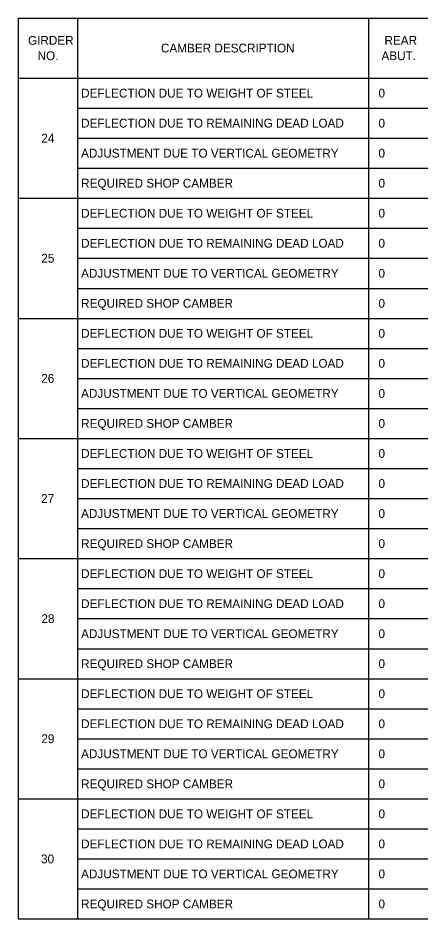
# Model space of a CAD drawing. Extents: x 3 to 33.4, y 0.9 to 20.5.
# Drawn here: x 3 to 10.19, y 4.69 to 20.5 of the extents above; entities that cross this region are included whole.
import ezdxf

# ---------------------------------------------------------------- set-up
doc = ezdxf.new("R2010")
doc.units = 0
doc.layers.add('BR_X_Beam_Object', color=7, linetype='Continuous')
doc.layers.add('BR_X_Slab_Object', color=7, linetype='Continuous')

msp = doc.modelspace()

# ---------------------------------------------------------------- linework, layer by layer
at = {"layer": 'BR_X_Slab_Object'}
for p, q in [((3, 20.5), (5.319, 20.5)), ((3, 20.5), (3, 4.688)), ((4.041, 20.5), (4.041, 4.688)), ((5.319, 20.5), (10.194, 20.5)), ((9.153, 20.5), (9.153, 4.688)), ((3, 19.446), (5.319, 19.446)), ((5.319, 19.446), (10.194, 19.446)), ((4.041, 18.919), (5.319, 18.919)), ((5.319, 18.919), (10.194, 18.919)), ((4.041, 18.392), (5.319, 18.392)), ((5.319, 18.392), (10.194, 18.392)), ((4.041, 17.865), (5.319, 17.865)), ((5.319, 17.865), (10.194, 17.865)), ((3, 17.338), (5.319, 17.338)), ((5.319, 17.338), (10.194, 17.338)), ((4.041, 16.811), (5.319, 16.811)), ((5.319, 16.811), (10.194, 16.811)), ((4.041, 16.284), (5.319, 16.284)), ((5.319, 16.284), (10.194, 16.284)), ((4.041, 15.756), (5.319, 15.756)), ((5.319, 15.756), (10.194, 15.756)), ((3, 15.229), (5.319, 15.229)), ((5.319, 15.229), (10.194, 15.229)), ((4.041, 14.702), (5.319, 14.702)), ((5.319, 14.702), (10.194, 14.702)), ((4.041, 14.175), (5.319, 14.175)), ((5.319, 14.175), (10.194, 14.175)), ((4.041, 13.648), (5.319, 13.648)), ((5.319, 13.648), (10.194, 13.648)), ((3, 13.121), (5.319, 13.121)), ((5.319, 13.121), (10.194, 13.121)), ((4.041, 12.594), (5.319, 12.594)), ((5.319, 12.594), (10.194, 12.594)), ((4.041, 12.067), (5.319, 12.067)), ((5.319, 12.067), (10.194, 12.067)), ((4.041, 11.54), (5.319, 11.54)), ((5.319, 11.54), (10.194, 11.54)), ((3, 11.013), (5.319, 11.013)), ((5.319, 11.013), (10.194, 11.013)), ((4.041, 10.486), (5.319, 10.486)), ((5.319, 10.486), (10.194, 10.486)), ((4.041, 9.959), (5.319, 9.959)), ((5.319, 9.959), (10.194, 9.959)), ((4.041, 9.432), (5.319, 9.432)), ((5.319, 9.432), (10.194, 9.432)), ((3, 8.905), (5.319, 8.905)), ((5.319, 8.905), (10.194, 8.905)), ((4.041, 8.378), (5.319, 8.378)), ((5.319, 8.378), (10.194, 8.378)), ((4.041, 7.851), (5.319, 7.851)), ((5.319, 7.851), (10.194, 7.851)), ((4.041, 7.324), (5.319, 7.324)), ((5.319, 7.324), (10.194, 7.324)), ((3, 6.796), (5.319, 6.796)), ((5.319, 6.796), (10.194, 6.796)), ((4.041, 6.269), (5.319, 6.269)), ((5.319, 6.269), (10.194, 6.269)), ((4.041, 5.742), (5.319, 5.742)), ((5.319, 5.742), (10.194, 5.742)), ((4.041, 5.215), (5.319, 5.215)), ((5.319, 5.215), (10.194, 5.215)), ((3, 4.688), (5.319, 4.688)), ((5.319, 4.688), (10.194, 4.688))]:
    msp.add_line(p, q, dxfattribs=at)

# ---------------------------------------------------------------- texts
at = {"layer": 'BR_X_Beam_Object'}
for s, p in [('GIRDER', (3.175, 20.031)), ('REAR', (9.431, 20.031)), ('CAMBER DESCRIPTION', (5.508, 19.896)), ('NO.', (3.343, 19.761)), ('ABUT.', (9.378, 19.761)), ('DEFLECTION DUE TO WEIGHT OF STEEL', (4.107, 19.105)), ('0      ', (9.326, 19.105)), ('DEFLECTION DUE TO REMAINING DEAD LOAD', (4.107, 18.578)), ('0      ', (9.326, 18.578)), ('24', (3.41, 18.315)), ('ADJUSTMENT DUE TO VERTICAL GEOMETRY', (4.107, 18.051)), ('0      ', (9.326, 18.051)), ('REQUIRED SHOP CAMBER', (4.107, 17.524)), ('0      ', (9.326, 17.524)), ('DEFLECTION DUE TO WEIGHT OF STEEL', (4.107, 16.997)), ('0      ', (9.326, 16.997)), ('DEFLECTION DUE TO REMAINING DEAD LOAD', (4.107, 16.47)), ('0      ', (9.326, 16.47)), ('25', (3.409, 16.207)), ('ADJUSTMENT DUE TO VERTICAL GEOMETRY', (4.107, 15.943)), ('0      ', (9.326, 15.943)), ('REQUIRED SHOP CAMBER', (4.107, 15.416)), ('0      ', (9.326, 15.416)), ('DEFLECTION DUE TO WEIGHT OF STEEL', (4.107, 14.889)), ('0      ', (9.326, 14.889)), ('DEFLECTION DUE TO REMAINING DEAD LOAD', (4.107, 14.362)), ('0      ', (9.326, 14.362)), ('26', (3.408, 14.098)), ('ADJUSTMENT DUE TO VERTICAL GEOMETRY', (4.107, 13.835)), ('0      ', (9.326, 13.835)), ('REQUIRED SHOP CAMBER', (4.107, 13.308)), ('0      ', (9.326, 13.308)), ('DEFLECTION DUE TO WEIGHT OF STEEL', (4.107, 12.781)), ('0      ', (9.326, 12.781)), ('DEFLECTION DUE TO REMAINING DEAD LOAD', (4.107, 12.254)), ('0      ', (9.326, 12.254)), ('27', (3.405, 11.99)), ('ADJUSTMENT DUE TO VERTICAL GEOMETRY', (4.107, 11.727)), ('0      ', (9.326, 11.727)), ('REQUIRED SHOP CAMBER', (4.107, 11.199)), ('0      ', (9.326, 11.199)), ('DEFLECTION DUE TO WEIGHT OF STEEL', (4.107, 10.672)), ('0      ', (9.326, 10.672)), ('DEFLECTION DUE TO REMAINING DEAD LOAD', (4.107, 10.145)), ('0      ', (9.326, 10.145)), ('28', (3.411, 9.882)), ('ADJUSTMENT DUE TO VERTICAL GEOMETRY', (4.107, 9.618)), ('0      ', (9.326, 9.618)), ('REQUIRED SHOP CAMBER', (4.107, 9.091)), ('0      ', (9.326, 9.091)), ('DEFLECTION DUE TO WEIGHT OF STEEL', (4.107, 8.564)), ('0      ', (9.326, 8.564)), ('DEFLECTION DUE TO REMAINING DEAD LOAD', (4.107, 8.037)), ('0      ', (9.326, 8.037)), ('29', (3.409, 7.774)), ('ADJUSTMENT DUE TO VERTICAL GEOMETRY', (4.107, 7.51)), ('0      ', (9.326, 7.51)), ('REQUIRED SHOP CAMBER', (4.107, 6.983)), ('0      ', (9.326, 6.983)), ('DEFLECTION DUE TO WEIGHT OF STEEL', (4.107, 6.456)), ('0      ', (9.326, 6.456)), ('DEFLECTION DUE TO REMAINING DEAD LOAD', (4.107, 5.929)), ('0      ', (9.326, 5.929)), ('30', (3.404, 5.665)), ('ADJUSTMENT DUE TO VERTICAL GEOMETRY', (4.107, 5.402)), ('0      ', (9.326, 5.402)), ('REQUIRED SHOP CAMBER', (4.107, 4.875)), ('0      ', (9.326, 4.875))]:
    msp.add_text(s, height=0.154, dxfattribs=at).set_placement(p)

doc.saveas('drawing.dxf')
